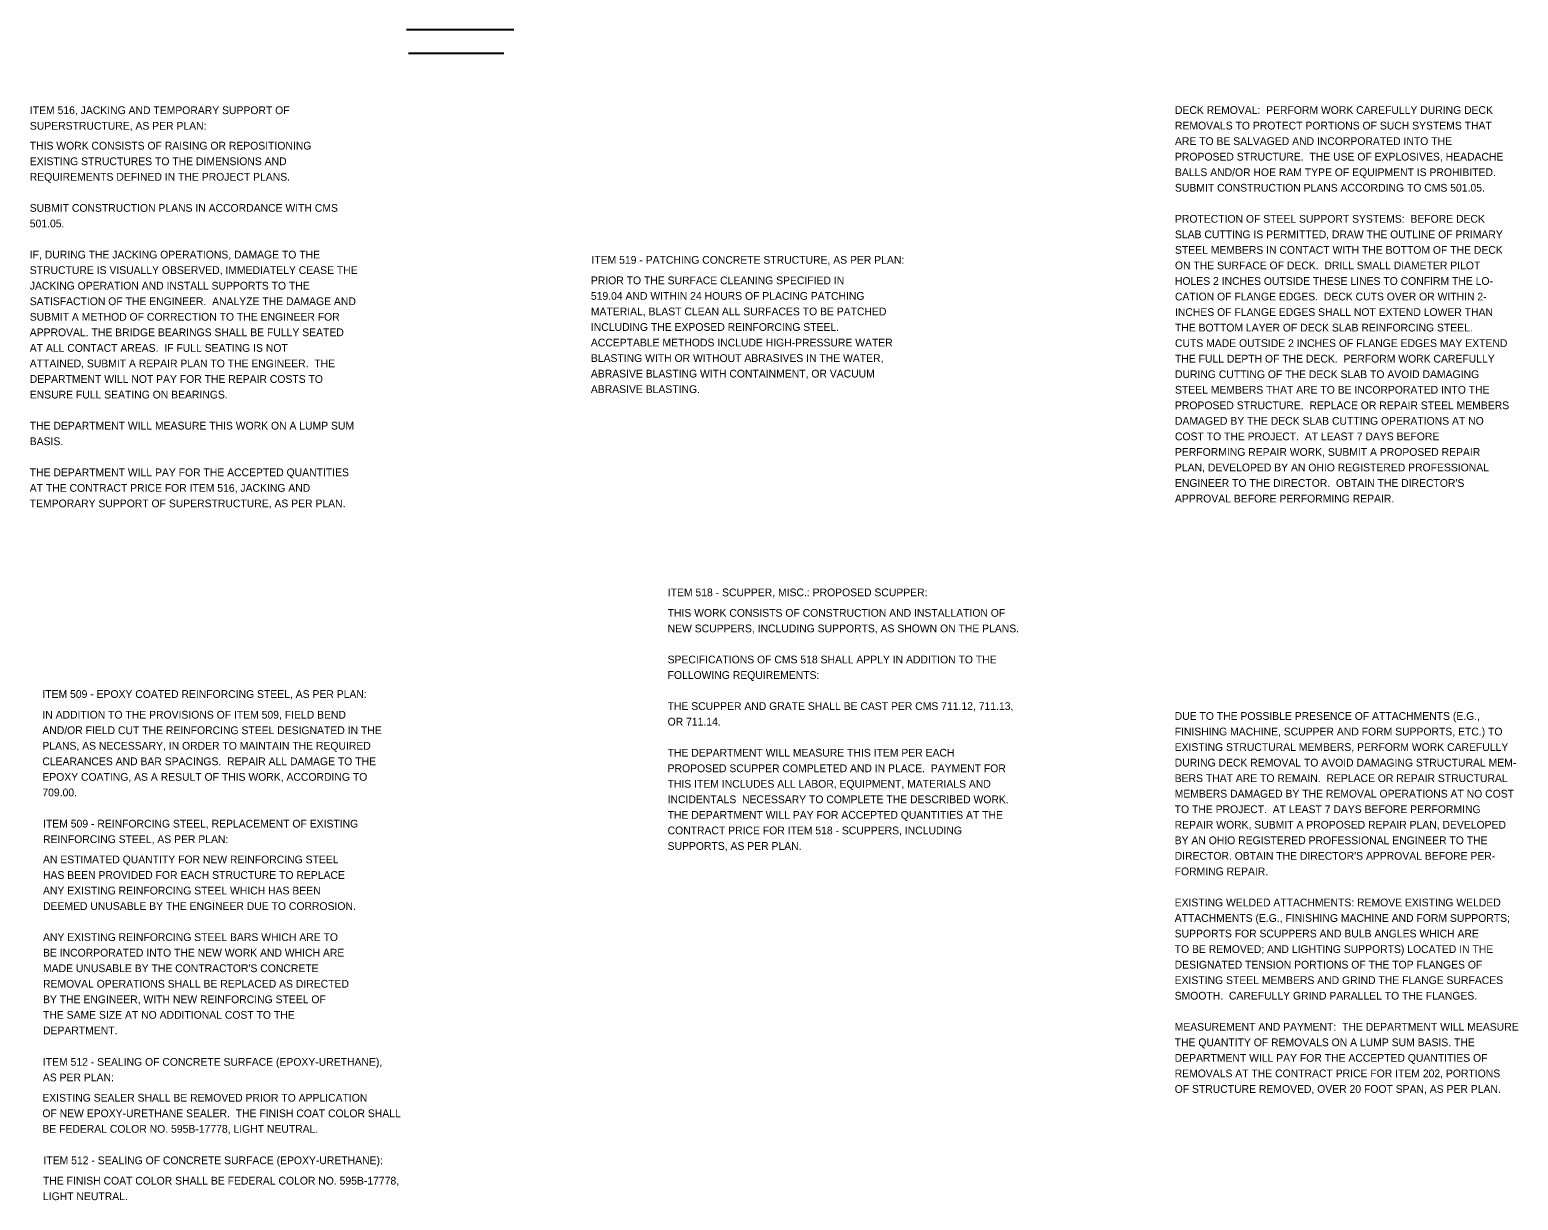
# Model space of a CAD drawing. Extents: x 8.9 to 72, y -18.6 to 3.4.
# Drawn here: x 45.18 to 72, y -17.7 to 3.39 of the extents above; entities that cross this region are included whole.
import ezdxf

# ---------------------------------------------------------------- set-up
doc = ezdxf.new("R2010")
doc.units = 0
doc.layers.add('BR_P_Gen_Text', color=7, linetype='Continuous')
doc.layers.add('SH_Text', color=7, linetype='Continuous')

msp = doc.modelspace()

# ---------------------------------------------------------------- linework, layer by layer
at = {"layer": 'BR_P_Gen_Text'}
for p, q in [((53.902, 3.39), (51.97, 3.39)), ((53.725, 2.963), (52.003, 2.963))]:
    msp.add_line(p, q, dxfattribs=at)

# ---------------------------------------------------------------- texts
for s, rotation, p in [('ITEM 516, JACKING AND TEMPORARY SUPPORT OF ', 0, (45.18, 1.871)), ('SUPERSTRUCTURE, AS PER PLAN:', 0, (45.18, 1.59)), ('THIS WORK CONSISTS OF RAISING OR REPOSITIONING ', 0, (45.178, 1.232)), ('EXISTING STRUCTURES TO THE DIMENSIONS AND ', 0, (45.178, 0.951)), ('REQUIREMENTS DEFINED IN THE PROJECT PLANS.', 0, (45.178, 0.671)), ('SUBMIT CONSTRUCTION PLANS IN ACCORDANCE WITH CMS ', 0, (45.178, 0.111)), ('501.05.', 0, (45.178, -0.17)), ('IF, DURING THE JACKING OPERATIONS, DAMAGE TO THE ', 0, (45.178, -0.73)), ('STRUCTURE IS VISUALLY OBSERVED, IMMEDIATELY CEASE THE ', 0, (45.178, -1.01)), ('PRIOR TO THE SURFACE CLEANING SPECIFIED IN ', 359.9999, (55.291, -1.195)), ('JACKING OPERATION AND INSTALL SUPPORTS TO THE ', 0, (45.178, -1.291)), ('519.04 AND WITHIN 24 HOURS OF PLACING PATCHING ', 359.9999, (55.291, -1.475)), ('SATISFACTION OF THE ENGINEER.  ANALYZE THE DAMAGE AND ', 0, (45.178, -1.571)), ('SUBMIT A METHOD OF CORRECTION TO THE ENGINEER FOR ', 0, (45.178, -1.851)), ('MATERIAL, BLAST CLEAN ALL SURFACES TO BE PATCHED ', 359.9999, (55.291, -1.755)), ('APPROVAL. THE BRIDGE BEARINGS SHALL BE FULLY SEATED ', 0, (45.178, -2.131)), ('INCLUDING THE EXPOSED REINFORCING STEEL.  ', 359.9999, (55.291, -2.035)), ('AT ALL CONTACT AREAS.  IF FULL SEATING IS NOT ', 0, (45.178, -2.412)), ('ACCEPTABLE METHODS INCLUDE HIGH-PRESSURE WATER ', 359.9999, (55.291, -2.315)), ('ATTAINED, SUBMIT A REPAIR PLAN TO THE ENGINEER.  THE ', 0, (45.178, -2.692)), ('BLASTING WITH OR WITHOUT ABRASIVES IN THE WATER, ', 359.9999, (55.291, -2.595)), ('DEPARTMENT WILL NOT PAY FOR THE REPAIR COSTS TO ', 0, (45.178, -2.972)), ('ABRASIVE BLASTING WITH CONTAINMENT, OR VACUUM ', 359.9999, (55.291, -2.875)), ('ENSURE FULL SEATING ON BEARINGS.', 0, (45.178, -3.253)), ('ABRASIVE BLASTING.', 359.9999, (55.291, -3.155)), ('THE DEPARTMENT WILL MEASURE THIS WORK ON A LUMP SUM ', 0, (45.178, -3.813)), ('BASIS.', 0, (45.178, -4.093)), ('THE DEPARTMENT WILL PAY FOR THE ACCEPTED QUANTITIES ', 0, (45.178, -4.654)), ('AT THE CONTRACT PRICE FOR ITEM 516, JACKING AND ', 0, (45.178, -4.934)), ('TEMPORARY SUPPORT OF SUPERSTRUCTURE, AS PER PLAN.', 0, (45.178, -5.214)), ('AN ESTIMATED QUANTITY FOR NEW REINFORCING STEEL ', 359.9999, (45.417, -11.629)), ('HAS BEEN PROVIDED FOR EACH STRUCTURE TO REPLACE ', 359.9999, (45.417, -11.909)), ('ANY EXISTING REINFORCING STEEL WHICH HAS BEEN ', 359.9999, (45.417, -12.189)), ('DEEMED UNUSABLE BY THE ENGINEER DUE TO CORROSION.', 359.9999, (45.417, -12.469)), ('ANY EXISTING REINFORCING STEEL BARS WHICH ARE TO ', 359.9999, (45.417, -13.029)), ('BE INCORPORATED INTO THE NEW WORK AND WHICH ARE ', 359.9999, (45.417, -13.309)), ("MADE UNUSABLE BY THE CONTRACTOR'S CONCRETE ", 359.9999, (45.417, -13.589)), ('REMOVAL OPERATIONS SHALL BE REPLACED AS DIRECTED ', 359.9999, (45.417, -13.869)), ('BY THE ENGINEER, WITH NEW REINFORCING STEEL OF ', 359.9999, (45.417, -14.149)), ('THE SAME SIZE AT NO ADDITIONAL COST TO THE ', 359.9999, (45.417, -14.429)), ('DEPARTMENT.', 359.9999, (45.417, -14.709))]:
    msp.add_text(s, height=0.14, rotation=rotation, dxfattribs=at).set_placement(p)
for s, p in [('DECK REMOVAL:  PERFORM WORK CAREFULLY DURING DECK', (65.818, 1.874)), ('REMOVALS TO PROTECT PORTIONS OF SUCH SYSTEMS THAT ', (65.818, 1.594)), ('ARE TO BE SALVAGED AND INCORPORATED INTO THE ', (65.818, 1.314)), ('PROPOSED STRUCTURE.  THE USE OF EXPLOSIVES, HEADACHE ', (65.818, 1.034)), ('BALLS AND/OR HOE RAM TYPE OF EQUIPMENT IS PROHIBITED.  ', (65.818, 0.754)), ('SUBMIT CONSTRUCTION PLANS ACCORDING TO CMS 501.05.', (65.818, 0.474)), ('PROTECTION OF STEEL SUPPORT SYSTEMS:  BEFORE DECK', (65.818, -0.086)), ('SLAB CUTTING IS PERMITTED, DRAW THE OUTLINE OF PRIMARY', (65.818, -0.366)), ('STEEL MEMBERS IN CONTACT WITH THE BOTTOM OF THE DECK', (65.818, -0.646)), ('ITEM 519 - PATCHING CONCRETE STRUCTURE, AS PER PLAN:', (55.301, -0.825)), ('ON THE SURFACE OF DECK.  DRILL SMALL DIAMETER PILOT', (65.818, -0.926)), ('HOLES 2 INCHES OUTSIDE THESE LINES TO CONFIRM THE LO-', (65.818, -1.206)), ('CATION OF FLANGE EDGES.  DECK CUTS OVER OR WITHIN 2-', (65.818, -1.486)), ('INCHES OF FLANGE EDGES SHALL NOT EXTEND LOWER THAN ', (65.818, -1.766)), ('THE BOTTOM LAYER OF DECK SLAB REINFORCING STEEL.  ', (65.818, -2.046)), ('CUTS MADE OUTSIDE 2 INCHES OF FLANGE EDGES MAY EXTEND ', (65.818, -2.326)), ('THE FULL DEPTH OF THE DECK.  PERFORM WORK CAREFULLY ', (65.818, -2.606)), ('DURING CUTTING OF THE DECK SLAB TO AVOID DAMAGING ', (65.818, -2.886)), ('STEEL MEMBERS THAT ARE TO BE INCORPORATED INTO THE ', (65.818, -3.166)), ('PROPOSED STRUCTURE.  REPLACE OR REPAIR STEEL MEMBERS ', (65.818, -3.446)), ('DAMAGED BY THE DECK SLAB CUTTING OPERATIONS AT NO ', (65.818, -3.726)), ('COST TO THE PROJECT.  AT LEAST 7 DAYS BEFORE ', (65.818, -4.006)), ('PERFORMING REPAIR WORK, SUBMIT A PROPOSED REPAIR ', (65.818, -4.286)), ('PLAN, DEVELOPED BY AN OHIO REGISTERED PROFESSIONAL', (65.818, -4.566)), ("ENGINEER TO THE DIRECTOR.  OBTAIN THE DIRECTOR'S ", (65.818, -4.846)), ('APPROVAL BEFORE PERFORMING REPAIR.', (65.818, -5.126)), ('ITEM 518 - SCUPPER, MISC.: PROPOSED SCUPPER:', (56.677, -6.817)), ('ITEM 509 - EPOXY COATED REINFORCING STEEL, AS PER PLAN:', (45.405, -8.648)), ('IN ADDITION TO THE PROVISIONS OF ITEM 509, FIELD BEND ', (45.405, -9.021)), ('DUE TO THE POSSIBLE PRESENCE OF ATTACHMENTS (E.G.,', (65.813, -9.044)), ('AND/OR FIELD CUT THE REINFORCING STEEL DESIGNATED IN THE ', (45.405, -9.301)), ('FINISHING MACHINE, SCUPPER AND FORM SUPPORTS, ETC.) TO', (65.813, -9.324)), ('PLANS, AS NECESSARY, IN ORDER TO MAINTAIN THE REQUIRED ', (45.405, -9.581)), ('EXISTING STRUCTURAL MEMBERS, PERFORM WORK CAREFULLY', (65.813, -9.604)), ('CLEARANCES AND BAR SPACINGS.  REPAIR ALL DAMAGE TO THE ', (45.405, -9.861)), ('DURING DECK REMOVAL TO AVOID DAMAGING STRUCTURAL MEM-', (65.813, -9.884)), ('EPOXY COATING, AS A RESULT OF THIS WORK, ACCORDING TO ', (45.405, -10.141)), ('BERS THAT ARE TO REMAIN.  REPLACE OR REPAIR STRUCTURAL', (65.813, -10.164)), ('709.00.', (45.405, -10.421)), ('MEMBERS DAMAGED BY THE REMOVAL OPERATIONS AT NO COST', (65.813, -10.444)), ('TO THE PROJECT.  AT LEAST 7 DAYS BEFORE PERFORMING', (65.813, -10.724)), ('ITEM 509 - REINFORCING STEEL, REPLACEMENT OF EXISTING', (45.418, -10.984)), ('REPAIR WORK, SUBMIT A PROPOSED REPAIR PLAN, DEVELOPED', (65.813, -11.004)), ('REINFORCING STEEL, AS PER PLAN:', (45.418, -11.264)), ('BY AN OHIO REGISTERED PROFESSIONAL ENGINEER TO THE', (65.813, -11.284)), ("DIRECTOR. OBTAIN THE DIRECTOR'S APPROVAL BEFORE PER-", (65.813, -11.564)), ('FORMING REPAIR.', (65.813, -11.844)), ('EXISTING WELDED ATTACHMENTS: REMOVE EXISTING WELDED', (65.813, -12.404)), ('ATTACHMENTS (E.G., FINISHING MACHINE AND FORM SUPPORTS;', (65.813, -12.684)), ('SUPPORTS FOR SCUPPERS AND BULB ANGLES WHICH ARE', (65.813, -12.964)), ('TO BE REMOVED; AND LIGHTING SUPPORTS) LOCATED IN THE', (65.813, -13.244)), ('DESIGNATED TENSION PORTIONS OF THE TOP FLANGES OF', (65.813, -13.524)), ('EXISTING STEEL MEMBERS AND GRIND THE FLANGE SURFACES', (65.813, -13.804)), ('SMOOTH.  CAREFULLY GRIND PARALLEL TO THE FLANGES.', (65.813, -14.084)), ('MEASUREMENT AND PAYMENT:  THE DEPARTMENT WILL MEASURE', (65.813, -14.644)), ('THE QUANTITY OF REMOVALS ON A LUMP SUM BASIS. THE', (65.813, -14.924)), ('ITEM 512 - SEALING OF CONCRETE SURFACE (EPOXY-URETHANE),', (45.414, -15.276)), ('DEPARTMENT WILL PAY FOR THE ACCEPTED QUANTITIES OF', (65.813, -15.204)), ('AS PER PLAN:', (45.414, -15.556)), ('REMOVALS AT THE CONTRACT PRICE FOR ITEM 202, PORTIONS', (65.813, -15.484)), ('EXISTING SEALER SHALL BE REMOVED PRIOR TO APPLICATION', (45.405, -15.923)), ('OF STRUCTURE REMOVED, OVER 20 FOOT SPAN, AS PER PLAN.', (65.813, -15.764)), ('OF NEW EPOXY-URETHANE SEALER.  THE FINISH COAT COLOR SHALL ', (45.405, -16.203)), ('BE FEDERAL COLOR NO. 595B-17778, LIGHT NEUTRAL.', (45.405, -16.483)), ('ITEM 512 - SEALING OF CONCRETE SURFACE (EPOXY-URETHANE):', (45.425, -17.05)), ('THE FINISH COAT COLOR SHALL BE FEDERAL COLOR NO. 595B-17778, ', (45.416, -17.417)), ('LIGHT NEUTRAL.', (45.416, -17.697))]:
    msp.add_text(s, height=0.14, dxfattribs=at).set_placement(p)
at = {"layer": 'SH_Text'}
for s, p in [('THIS WORK CONSISTS OF CONSTRUCTION AND INSTALLATION OF', (56.674, -7.186)), ('NEW SCUPPERS, INCLUDING SUPPORTS, AS SHOWN ON THE PLANS.', (56.674, -7.466)), ('SPECIFICATIONS OF CMS 518 SHALL APPLY IN ADDITION TO THE', (56.674, -8.026)), ('FOLLOWING REQUIREMENTS:', (56.674, -8.306)), ('THE SCUPPER AND GRATE SHALL BE CAST PER CMS 711.12, 711.13, ', (56.674, -8.866)), ('OR 711.14.', (56.674, -9.146)), ('THE DEPARTMENT WILL MEASURE THIS ITEM PER EACH', (56.674, -9.706)), ('PROPOSED SCUPPER COMPLETED AND IN PLACE.  PAYMENT FOR', (56.674, -9.986)), ('THIS ITEM INCLUDES ALL LABOR, EQUIPMENT, MATERIALS AND', (56.674, -10.266)), ('INCIDENTALS  NECESSARY TO COMPLETE THE DESCRIBED WORK.', (56.674, -10.546)), ('THE DEPARTMENT WILL PAY FOR ACCEPTED QUANTITIES AT THE', (56.674, -10.826)), ('CONTRACT PRICE FOR ITEM 518 - SCUPPERS, INCLUDING ', (56.674, -11.106)), ('SUPPORTS, AS PER PLAN. ', (56.674, -11.386))]:
    msp.add_text(s, height=0.14, dxfattribs=at).set_placement(p)

doc.saveas('drawing.dxf')
